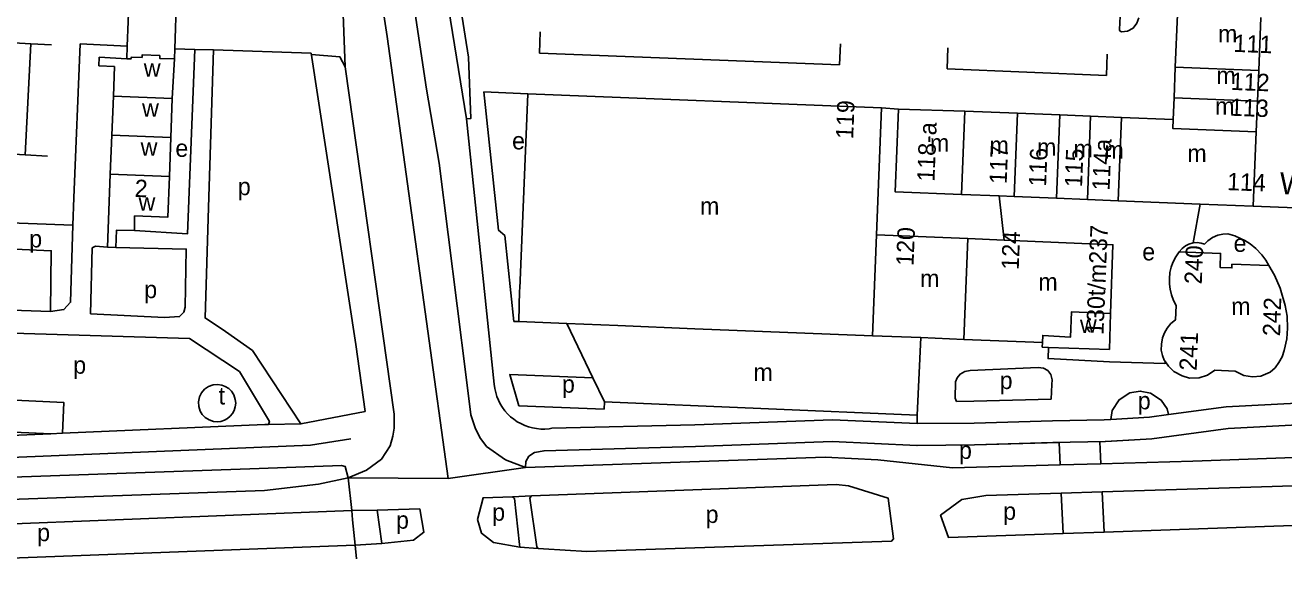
# Model space of a CAD drawing. Extents: x 159675 to 162108, y 386471 to 388472.
# Drawn here: x 160845.9 to 161135.6, y 386475.2 to 386600.8 of the extents above; entities that cross this region are included whole.
import ezdxf

# ---------------------------------------------------------------- set-up
doc = ezdxf.new("R2010")
doc.units = 0
for name, color, linetype in [('BLT_Basislijn', 7, 'Continuous'), ('BLT_Bebouwing', 7, 'Continuous'), ('BLT_Centroide', 7, 'Continuous'), ('BLT_Huisnummer', 7, 'Continuous'), ('BLT_Huisnummer_reeks', 7, 'Continuous'), ('BLT_Onderdoorgang_en_onderverdeling', 7, 'Continuous'), ('BLT_Onderverdeling_panden', 7, 'Continuous'), ('BLT_Straatnaam', 7, 'Continuous'), ('BLT_Vlakafsluiter', 7, 'Continuous')]:
    doc.layers.add(name, color=color, linetype=linetype)

msp = doc.modelspace()

# ---------------------------------------------------------------- linework, layer by layer
at = {"layer": 'BLT_Basislijn'}
for p, q in [((160830.12, 386597.53), (160847.17, 386596.56)), ((160845.89, 386570.96), (160847.17, 386596.56)), ((160847.17, 386596.56), (160851.97, 386596.27)), ((160858.53, 386596.53), (160869.37, 386595.96)), ((160964.25, 386594.41), (160964.44, 386599.3)), ((161033.36, 386591.67), (161033.55, 386596.56)), ((160884.9, 386595.25), (160880.3, 386595.37)), ((160884.9, 386595.25), (160889.21, 386595.11)), ((160888.04, 386558.85), (160889.21, 386595.11)), ((160911.7, 386594.39), (160889.21, 386595.11)), ((161033.36, 386591.67), (160964.25, 386594.41)), ((161058.09, 386590.73), (161058.28, 386595.62)), ((161094.78, 386589.27), (161094.97, 386594.16)), ((161094.78, 386589.27), (161058.09, 386590.73)), ((161043, 386581.8), (161046.89, 386581.5)), ((160840.57, 386571.29), (160845.89, 386570.96)), ((160845.89, 386570.96), (160851.03, 386570.64)), ((161071.22, 386551.34), (161070.07, 386561.5)), ((161114.76, 386550.7), (161116.36, 386559.64)), ((161083.87, 386504.76), (161084.09, 386499.61)), ((161093.24, 386504.92), (161093.48, 386499.86)), ((161084.09, 386499.61), (161093.48, 386499.86)), ((160958.05, 386492.27), (160962.4, 386492.43)), ((160958.36, 386491.99), (160958.05, 386492.27)), ((160962.18, 386492.16), (160962.4, 386492.43)), ((161093.79, 386493.39), (161084.38, 386493.1)), ((161084.38, 386493.1), (161084.8, 386483.79)), ((161093.79, 386493.39), (161094.24, 386484.13)), ((160921.07, 386489.08), (160779.48, 386483.45)), ((160921.07, 386489.08), (160926.93, 386489.2)), ((160921.82, 386481.09), (160921.26, 386486.92)), ((160928.01, 386481.46), (160926.93, 386489.2)), ((161084.8, 386483.79), (161094.24, 386484.13)), ((160921.82, 386481.09), (160928.01, 386481.46)), ((160959.65, 386481.23), (160959.71, 386480.64)), ((160959.71, 386480.64), (160964, 386480.35)), ((160964, 386480.35), (160965.18, 386480.28))]:
    msp.add_line(p, q, dxfattribs=at)
for points in [[(160911.07, 386716.12), (160929.2, 386598.21), (160943.22, 386496.43)], [(160947.44, 386579.29), (160938.77, 386632.83), (160941.6, 386633.21)], [(160947.96, 386593.46), (160941.6, 386633.21)], [(160935.42, 386623.87), (160935.12, 386607.08), (160938.24, 386586.05), (160941.18, 386569.03), (160947.36, 386519.8), (160948.5, 386511.14)], [(161098.01, 386604.46), (161097.77, 386599.84)], [(161098.28, 386599.28), (161099.62, 386599.44), (161100.89, 386600.14), (161101.8, 386601.26), (161102.21, 386602.54)], [(161097.77, 386599.84), (161097.81, 386599.64), (161097.92, 386599.46), (161098.09, 386599.33), (161098.28, 386599.28)], [(160856.88, 386554.78), (160857.06, 386561.07), (160858.53, 386596.53)], [(160871.01, 386553.55), (160883.24, 386552.77), (160884.9, 386595.25)], [(160892, 386530.28), (160898.18, 386525.91), (160909.35, 386509.02), (160924.12, 386511.9), (160921.99, 386527.31), (160911.7, 386594.39)], [(160911.75, 386594.09), (160918.33, 386593.52), (160919.57, 386591.24)], [(160919.57, 386591.24), (160930.79, 386511.26), (160930.78, 386508.07), (160930.5, 386506.24), (160929.91, 386503.98)], [(160947.96, 386593.46), (160948.43, 386579.3), (160947.44, 386579.29)], [(160959.51, 386532.57), (160958.38, 386532.63), (160956.3, 386552.37), (160954.85, 386553.62), (160951.46, 386585.44), (160961.57, 386585.04)], [(160947.44, 386579.29), (160953.84, 386518.15)], [(160856.88, 386554.78), (160821.83, 386556.07), (160821.72, 386550.23), (160851.86, 386548.88), (160851.7, 386534.91)], [(160892, 386530.28), (160887.29, 386533.43), (160888.04, 386558.85)], [(160851.7, 386534.91), (160854.79, 386535.34), (160856.32, 386537.03), (160856.88, 386554.78)], [(161114.76, 386550.7), (161113.77, 386550.42), (161112.96, 386550.01), (161112.18, 386549.38), (161111.55, 386548.63)], [(161132.17, 386545.48), (161131.44, 386546.72), (161130.56, 386547.93), (161129.18, 386549.39), (161127.85, 386550.46), (161126.67, 386551.22), (161125.67, 386551.74), (161124.34, 386552.29), (161122.7, 386552.75), (161121.6, 386552.73), (161120.42, 386552.48), (161119.17, 386551.94), (161118.13, 386551.19), (161117.37, 386550.41), (161116.57, 386550.66), (161115.63, 386550.76), (161114.76, 386550.7)], [(160864.79, 386549.72), (160862.06, 386549.91), (160861.3, 386549.53), (160860.95, 386534.38), (160877.98, 386533.51), (160881.42, 386533.75), (160882.37, 386534.77), (160882.72, 386535.93), (160882.96, 386549.28), (160866.74, 386549.67)], [(160816.01, 386536.12), (160851.7, 386534.91)], [(160818.66, 386505.37), (160768.87, 386503.3), (160769.32, 386532.16), (160883.71, 386528.7), (160895.18, 386521.1), (160902.09, 386509.61), (160901.86, 386508.91), (160901.07, 386508.86), (160854.44, 386506.88)], [(161108.35, 386523.35), (161108.24, 386522.95), (161095.49, 386523.34), (161081.35, 386524.07), (161081.43, 386526.65)], [(160851.78, 386506.77), (160797.32, 386509.22), (160792.16, 386513.35), (160791.16, 386514.02), (160790.05, 386514.48), (160788.87, 386514.72), (160787.65, 386514.73), (160786.38, 386514.48), (160785.28, 386514.03), (160784.21, 386513.31), (160783.38, 386512.48), (160782.72, 386511.51), (160782.22, 386510.34), (160781.71, 386508.69), (160771.3, 386508.35), (160771.91, 386524.04), (160800.18, 386522.99), (160799.88, 386516.58), (160854.76, 386513.99), (160854.44, 386506.88)], [(161082.07, 386514.71), (161064.24, 386514.23), (161060.28, 386514.19), (161059.92, 386514.98), (161060.05, 386518.7), (161060.39, 386519.61), (161061.1, 386520.5), (161062.16, 386521.11), (161063.4, 386521.3), (161079.09, 386521.99), (161080.31, 386521.87), (161081.29, 386521.31), (161081.99, 386520.42), (161082.28, 386519.17), (161082.19, 386518.13), (161082.07, 386514.71)], [(160976.55, 386519.63), (160957.43, 386520.39), (160959.52, 386513.2), (160979.13, 386512.42), (160979.2, 386514.12)], [(160953.84, 386518.15), (160953.97, 386517.2), (160954.18, 386516.27), (160954.46, 386515.36), (160954.82, 386514.48), (160955.25, 386513.63), (160955.75, 386512.82), (160956.32, 386512.05), (160956.94, 386511.34), (160957.63, 386510.68), (160958.37, 386510.08), (160959.16, 386509.54), (160959.99, 386509.08), (160960.86, 386508.68), (160961.75, 386508.36), (160962.67, 386508.11), (160963.61, 386507.94), (160964.56, 386507.85), (160965.39, 386507.85)], [(161095.79, 386510.07), (161096.11, 386512.1), (161097.72, 386514.58), (161100.14, 386516.16), (161102.56, 386516.58), (161104.91, 386516.11), (161107.38, 386514.49), (161108.74, 386512.51), (161109.08, 386511.16)], [(161109.08, 386511.16), (161122.36, 386512.92), (161138.63, 386513.79), (161182.82, 386515.03)], [(160948.5, 386511.14), (160949.45, 386508.09), (160950.57, 386505.88), (160952.09, 386503.81), (160956.45, 386500.76), (160961.07, 386498.99)], [(160967.1, 386508.01), (161000, 386508.84), (161031.7, 386509.97), (161051.24, 386509.09)], [(161051.24, 386509.09), (161064.33, 386509.23), (161082.34, 386509.72), (161094.27, 386509.99), (161095.79, 386510.07)], [(161182.96, 386510.03), (161138.83, 386508.8), (161122.82, 386507.94), (161105.19, 386505.61), (161094.47, 386504.99), (161082.47, 386504.72), (161064.43, 386504.23), (161051.3, 386504.09)], [(161095.79, 386510.07), (161104.72, 386510.59), (161109.08, 386511.16)], [(160851.78, 386506.77), (160818.66, 386505.37)], [(160854.44, 386506.88), (160851.78, 386506.77)], [(160965.39, 386507.85), (160965.51, 386507.85), (160966.46, 386507.92), (160967.1, 386508.01)], [(161093.24, 386504.92), (161105.19, 386505.61), (161122.82, 386507.94), (161138.83, 386508.8)], [(161093.48, 386499.86), (161114.65, 386500.44), (161193.13, 386503.27), (161323.46, 386507.7)], [(160920.85, 386505.6), (160911.58, 386504.13), (160736.17, 386496.89), (160703.71, 386496.17), (160700, 386496.48)], [(160920.19, 386496.62), (160924.47, 386498.34), (160927.93, 386500.91), (160929.91, 386503.98)], [(160961.07, 386498.99), (160961.13, 386500.39), (160961.79, 386501.59), (160963.14, 386502.43), (160965.34, 386502.85), (161000.15, 386503.84), (161031.67, 386504.97), (161051.16, 386504.09)], [(161051.16, 386504.09), (161064.43, 386504.23), (161083.87, 386504.76)], [(160961.07, 386498.99), (161030, 386501.39), (161042.19, 386500.77), (161059.36, 386498.94), (161084.09, 386499.61)], [(160700, 386492.68), (160706.64, 386492.27), (160746.75, 386493.41), (160899.71, 386498.77)], [(160899.71, 386498.77), (160918.72, 386499.44), (160919.52, 386499.23), (160920.19, 386496.62)], [(161324.17, 386500.57), (161157.3, 386495.37), (161093.79, 386493.39)], [(160900.96, 386493.72), (160913.36, 386495.17), (160920.19, 386496.62)], [(161094.24, 386484.13), (161174.59, 386486.96), (161188.48, 386488.62), (161209.16, 386493.49), (161213.42, 386493.85), (161324.27, 386497.31)], [(160715.46, 386487.09), (160859.57, 386492.24), (160900.96, 386493.72)], [(160958.05, 386492.27), (160951.29, 386492.03), (160949.97, 386486.98), (160950.91, 386483.84), (160953.71, 386481.73), (160959.71, 386480.64)], [(160965.18, 386480.28), (160975.19, 386479.64), (161045.31, 386482.04), (161045.73, 386482.53), (161044.53, 386491.96), (161035.43, 386494.75), (161032.57, 386495.05), (160962.4, 386492.43)], [(161084.38, 386493.1), (161067.03, 386492.56), (161061.46, 386491.59), (161056.6, 386488), (161058.45, 386482.86), (161084.8, 386483.79)], [(160926.93, 386489.2), (160936.69, 386489.46), (160937.68, 386484.1), (160935.29, 386482.29), (160928.01, 386481.46)], [(160959.65, 386481.23), (160958.51, 386491.87), (160958.36, 386491.99)], [(160962.18, 386492.16), (160962.01, 386491.96), (160963.67, 386480.69), (160964, 386480.35)], [(160921.26, 386486.92), (160921.07, 386489.08)], [(160824.82, 386475.2), (160838.34, 386477.94), (160921.82, 386481.09)]]:
    msp.add_lwpolyline(points, dxfattribs=at)
msp.add_lwpolyline([(160886.01, 386515.26), (160886.48, 386516.19), (160887.18, 386517), (160888.11, 386517.64), (160889.14, 386518), (160890.18, 386518.1), (160891.17, 386517.95), (160891.93, 386517.67), (160892.75, 386517.14), (160893.36, 386516.53), (160893.9, 386515.69), (160894.24, 386514.68), (160894.33, 386513.81), (160894.24, 386512.92), (160893.97, 386512.1), (160893.59, 386511.41), (160893.06, 386510.77), (160892.43, 386510.25), (160891.74, 386509.88), (160890.88, 386509.61), (160890.06, 386509.53), (160889.26, 386509.6), (160888.22, 386509.94), (160887.31, 386510.51), (160886.65, 386511.2), (160886.19, 386511.95), (160885.83, 386513.02), (160885.77, 386514.12)], close=True, dxfattribs=at)
at = {"layer": 'BLT_Bebouwing'}
for p, q in [((160869.87, 386608.94), (160869.37, 386595.96)), ((160880.76, 386608.52), (160880.3, 386595.37)), ((161111.11, 386603.27), (161110.62, 386591.18)), ((161129.82, 386590.42), (161130.32, 386602.57)), ((160869.26, 386593.09), (160869.37, 386595.96)), ((160880.3, 386595.37), (160880.22, 386593.04)), ((160866.45, 386591.27), (160862.8, 386591.43)), ((160866.18, 386584.47), (160866.45, 386591.27)), ((161110.62, 386591.18), (161110.34, 386584.11)), ((161129.53, 386583.35), (161129.82, 386590.42)), ((160865.82, 386575.5), (160866.18, 386584.47)), ((161110.34, 386584.11), (161110.13, 386579.09)), ((161129.24, 386576.28), (161129.53, 386583.35)), ((161074.32, 386580.53), (161062.17, 386581.02)), ((161084.02, 386580.14), (161074.32, 386580.53)), ((161091.14, 386579.86), (161084.02, 386580.14)), ((161098.25, 386579.57), (161091.14, 386579.86)), ((161110.13, 386579.09), (161098.25, 386579.57)), ((160865.46, 386566.53), (160865.82, 386575.5)), ((160864.79, 386549.72), (160865.46, 386566.53)), ((161061.42, 386561.85), (161070.07, 386561.5)), ((161070.07, 386561.5), (161073.56, 386561.36)), ((161073.56, 386561.36), (161083.27, 386560.97)), ((161083.27, 386560.97), (161090.38, 386560.68)), ((161123.67, 386545.83), (161132.17, 386545.48)), ((160959.7, 386539.72), (160959.72, 386540.21)), ((160976.55, 386519.63), (160970.54, 386532.15)), ((161052.02, 386528.9), (161051.21, 386511.05)), ((160979.2, 386514.12), (160976.55, 386519.63)), ((161051.21, 386511.05), (160979.2, 386514.12))]:
    msp.add_line(p, q, dxfattribs=at)
for points in [[(160862.8, 386591.43), (160862.91, 386593.43), (160869.26, 386593.09)], [(160880.22, 386593.04), (160879.74, 386583.91)], [(160959.72, 386540.21), (160961.57, 386585.04)], [(161043, 386581.8), (160961.57, 386585.04)], [(160879.74, 386583.91), (160879.44, 386574.94)], [(161041.83, 386552.58), (161043, 386581.8)], [(161046.89, 386581.5), (161046.12, 386562.47), (161061.42, 386561.85)], [(161062.17, 386581.02), (161046.89, 386581.5)], [(161128.54, 386559.14), (161129.24, 386576.28)], [(160879.44, 386574.94), (160879.13, 386565.97)], [(160879.13, 386565.97), (160878.75, 386556.63), (160871.07, 386556.92), (160871.01, 386553.55)], [(161090.38, 386560.68), (161097.5, 386560.4)], [(161097.5, 386560.4), (161116.36, 386559.64)], [(161116.36, 386559.64), (161128.54, 386559.14)], [(160871.01, 386553.55), (160866.9, 386553.64), (160866.74, 386549.67)], [(161062.85, 386551.69), (161041.83, 386552.58)], [(161071.22, 386551.34), (161062.85, 386551.69)], [(161095.73, 386534.46), (161096.26, 386550.28), (161071.22, 386551.34)], [(160866.74, 386549.67), (160864.79, 386549.72)], [(161108.35, 386523.35), (161108.08, 386523.72), (161107.7, 386524.74), (161107.38, 386526.02), (161107.42, 386527.35), (161107.67, 386528.81), (161108.11, 386529.99), (161108.75, 386531.1), (161109.62, 386532.11), (161110.65, 386532.96), (161110.79, 386536.31), (161110.21, 386537.47), (161109.75, 386538.72), (161109.45, 386540.01), (161109.31, 386541.18), (161109.28, 386542.39), (161109.4, 386543.9), (161109.69, 386545.09), (161110.07, 386546.22), (161110.74, 386547.45), (161111.55, 386548.64)], [(161111.55, 386548.64), (161121.06, 386548.26), (161120.93, 386545.04), (161123.65, 386544.93), (161123.67, 386545.83)], [(161132.17, 386545.48), (161133.47, 386543.27), (161134.77, 386540.29), (161135.9, 386536.28), (161136.36, 386533.82), (161136.43, 386531.09), (161136.28, 386528.58), (161135.71, 386525.93), (161135.23, 386524.44), (161134.49, 386523.16), (161133.59, 386521.95), (161132.43, 386520.94), (161130.34, 386520.02), (161128.39, 386519.86), (161126.37, 386520.18), (161124.41, 386521.19), (161119.69, 386521.37), (161118.03, 386520.23), (161116.11, 386519.61), (161113.9, 386519.59), (161112.17, 386520.1), (161110.3, 386521.1), (161109.07, 386522.35), (161108.35, 386523.35)], [(160959.51, 386532.57), (160959.7, 386539.72)], [(161095.45, 386526.13), (161095.73, 386534.46)], [(160970.54, 386532.15), (160959.51, 386532.57)], [(161052.02, 386528.9), (161061.93, 386528.49)], [(161061.93, 386528.49), (161080.02, 386527.76)], [(161080.02, 386527.76), (161079.99, 386526.7), (161081.43, 386526.65)], [(161081.43, 386526.65), (161095.45, 386526.13)]]:
    msp.add_lwpolyline(points, dxfattribs=at)
at = {"layer": 'BLT_Onderdoorgang_en_onderverdeling'}
for points in [[(160869.26, 386593.09), (160870.2, 386593.04), (160870.34, 386593.44), (160872.78, 386593.38), (160872.8, 386593.98), (160876.87, 386593.8), (160876.84, 386593.18), (160880.22, 386593.04)], [(161080.02, 386527.76), (161080.13, 386529.38), (161086.54, 386529.03), (161086.77, 386534.83), (161095.73, 386534.46)]]:
    msp.add_lwpolyline(points, dxfattribs=at)
at = {"layer": 'BLT_Onderverdeling_panden'}
for p, q in [((161110.62, 386591.18), (161129.82, 386590.42)), ((160879.74, 386583.91), (160866.18, 386584.47)), ((161110.34, 386584.11), (161129.53, 386583.35)), ((161061.42, 386561.85), (161062.17, 386581.02)), ((161073.56, 386561.36), (161074.32, 386580.53)), ((161083.27, 386560.97), (161084.02, 386580.14)), ((161083.27, 386560.96), (161084.02, 386580.14)), ((161090.38, 386560.68), (161091.14, 386579.86)), ((161097.5, 386560.4), (161098.25, 386579.57)), ((160879.44, 386574.94), (160865.82, 386575.5)), ((160879.13, 386565.97), (160865.46, 386566.53)), ((161040.92, 386529.32), (161041.83, 386552.58)), ((161061.93, 386528.49), (161062.85, 386551.69)), ((161000, 386530.95), (160982.31, 386531.7))]:
    msp.add_line(p, q, dxfattribs=at)
for points in [[(161110.13, 386579.09), (161110.04, 386577.04), (161129.24, 386576.28)], [(160982.31, 386531.7), (160970.54, 386532.15)], [(161000, 386530.95), (161040.92, 386529.32)], [(161040.92, 386529.32), (161052.02, 386528.9)]]:
    msp.add_lwpolyline(points, dxfattribs=at)
at = {"layer": 'BLT_Vlakafsluiter'}
for p, q in [((160919.57, 386591.24), (160918.69, 386613.19)), ((161142.24, 386558.64), (161128.54, 386559.14)), ((161051.21, 386511.05), (161051.24, 386509.09)), ((160901.86, 386508.91), (160909.35, 386509.02)), ((160943.22, 386496.43), (160961.07, 386498.99)), ((160920.19, 386496.62), (160921.07, 386489.08)), ((160920.19, 386496.62), (160943.22, 386496.43)), ((160921.82, 386481.09), (160922.17, 386477.94))]:
    msp.add_line(p, q, dxfattribs=at)

# ---------------------------------------------------------------- texts
at = {"layer": 'BLT_Centroide'}
for s, p in [('m', (161120.46, 386596.84)), ('w', (160873.18, 386588.94)), ('m', (161120.08, 386587.25)), ('w', (160872.79, 386579.72)), ('m', (161119.79, 386580.19)), ('w', (160872.46, 386570.75)), ('e', (160880.45, 386570.5)), ('e', (160957.96, 386572.22)), ('m', (161054.14, 386571.72)), ('m', (161067.86, 386571.19)), ('m', (161078.8, 386570.75)), ('m', (161087.2, 386570.41)), ('m', (161094.31, 386570.12)), ('m', (161113.4, 386569.34)), ('p', (160894.82, 386561.68)), ('w', (160871.97, 386558.09)), ('m', (161001.22, 386557.19)), ('p', (160846.81, 386549.66)), ('e', (161124.04, 386548.63)), ('e', (161103.02, 386546.67)), ('m', (161051.88, 386540.52)), ('m', (161079.1, 386539.72)), ('p', (160873.28, 386537.97)), ('m', (161123.5, 386534.12)), ('p', (160856.93, 386520.58)), ('m', (161013.52, 386518.94)), ('p', (160969.44, 386516.21)), ('p', (161070.2, 386517.05)), ('t', (160890.39, 386513.5)), ('p', (161101.99, 386512.38)), ('p', (161060.83, 386500.96)), ('p', (160953.38, 386486.73)), ('p', (161002.51, 386486.22)), ('p', (161071, 386486.94)), ('p', (160931.24, 386484.9)), ('p', (160848.63, 386482.02))]:
    msp.add_text(s, height=4, dxfattribs=at).set_placement(p)
msp.add_text('w', height=4, rotation=1, dxfattribs=at).set_placement((161088.73, 386529.96))
at = {"layer": 'BLT_Huisnummer'}
for s, rotation, p in [('111', 357.7501, (161123.98, 386594.69)), ('112', 357.7471, (161123.34, 386585.93)), ('119', 87.5762, (161036.46, 386574.54)), ('113', 357.7473, (161123.15, 386579.99)), ('114a', 87.6613, (161095.49, 386562.68)), ('117', 87.7445, (161071.8, 386564.19)), ('116', 87.7504, (161080.87, 386563.59)), ('115', 87.7445, (161089.15, 386563.44)), ('114', 357.7485, (161122.48, 386562.86)), ('120', 87.7417, (161050.36, 386545.33))]:
    msp.add_text(s, height=4, rotation=rotation, dxfattribs=at).set_placement(p)
at = {"layer": 'BLT_Huisnummer_reeks'}
for s, rotation, p in [('118-a', 87.7474, (161055.18, 386564.73)), ('2', 357.6409, (160871.01, 386561.3)), ('124', 87.6673, (161074.57, 386544.43)), ('130t/m237', 87.6673, (161094.08, 386529.45)), ('240', 87.7215, (161116.71, 386541.13)), ('242', 88.1007, (161134.74, 386529.17)), ('241', 87.7271, (161115.54, 386521.2))]:
    msp.add_text(s, height=4, rotation=rotation, dxfattribs=at).set_placement(p)
at = {"layer": 'BLT_Straatnaam'}
msp.add_text('WINKELCENTRUM WOENSEL', height=5, rotation=357.5852, dxfattribs=at).set_placement((161134.57, 386561.96))

doc.saveas('drawing.dxf')
